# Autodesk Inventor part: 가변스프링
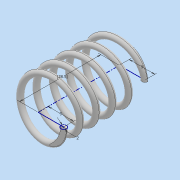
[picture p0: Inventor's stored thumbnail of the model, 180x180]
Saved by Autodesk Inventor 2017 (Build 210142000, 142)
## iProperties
Part Number: 가변스프링
Material: 일반
Document SubType Name: Modeling
Designer: MRC
Density: 1 g/cm^3
Appearance: 기본값
Mass: 0.874626 g
Surface Area: 17.7559 cm^2
Volume: 0.874626 cm^3
Author: MRC
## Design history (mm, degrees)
sketch "스케치1"
  geometry: L1 (0, 0)-(0, 28.5); L2 (0, 28.5)-(9, 28.5); L3 (0, 0)-(9, 0); C1 r 1 at (9, 0)
  constraints: 6 end point, 2 horizontal, 1 centre point, 1 coincident, 1 vertical
  dimensions: "d0" = 28.5 distance of L1.start L1.end (derived); "d1" = 9 distance of L1.end L2.end; "d2" = 9 distance of L1.start L3.end; "d3" = 2 diameter of C1
feature "코일1" sketch "스케치1" pitch "d4" = 10; turns "d6" = 5; dims "d5" = 28.5 (= d0), "d7" = 0, angle "d8" = 90 deg, angle "d9" = 90 deg, "d10" = 0, "d11" = 0
sketch "스케치2"
  geometry: L1 (28.5, 15)-(0, 15); L2 (0, 15)-(0, -15); L3 (0, -15)-(28.5, -15); L4 (28.5, -15)-(28.5, 15); 2 further points
  constraints: 8 end point, 2 parallel, 1 coincident, 1 horizontal, 1 midpoint, 1 perpendicular
  dimensions: "d12" = 28.5 distance of L2.end L3.end (= d0); "d13" = 30 distance of L3.end L1.start
extrude "돌출1" sketch "스케치2" stored distance "d14" = 0; taper "d15" = 0 deg
node "솔리드1"
